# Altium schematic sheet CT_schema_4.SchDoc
size 401 x 230 mm
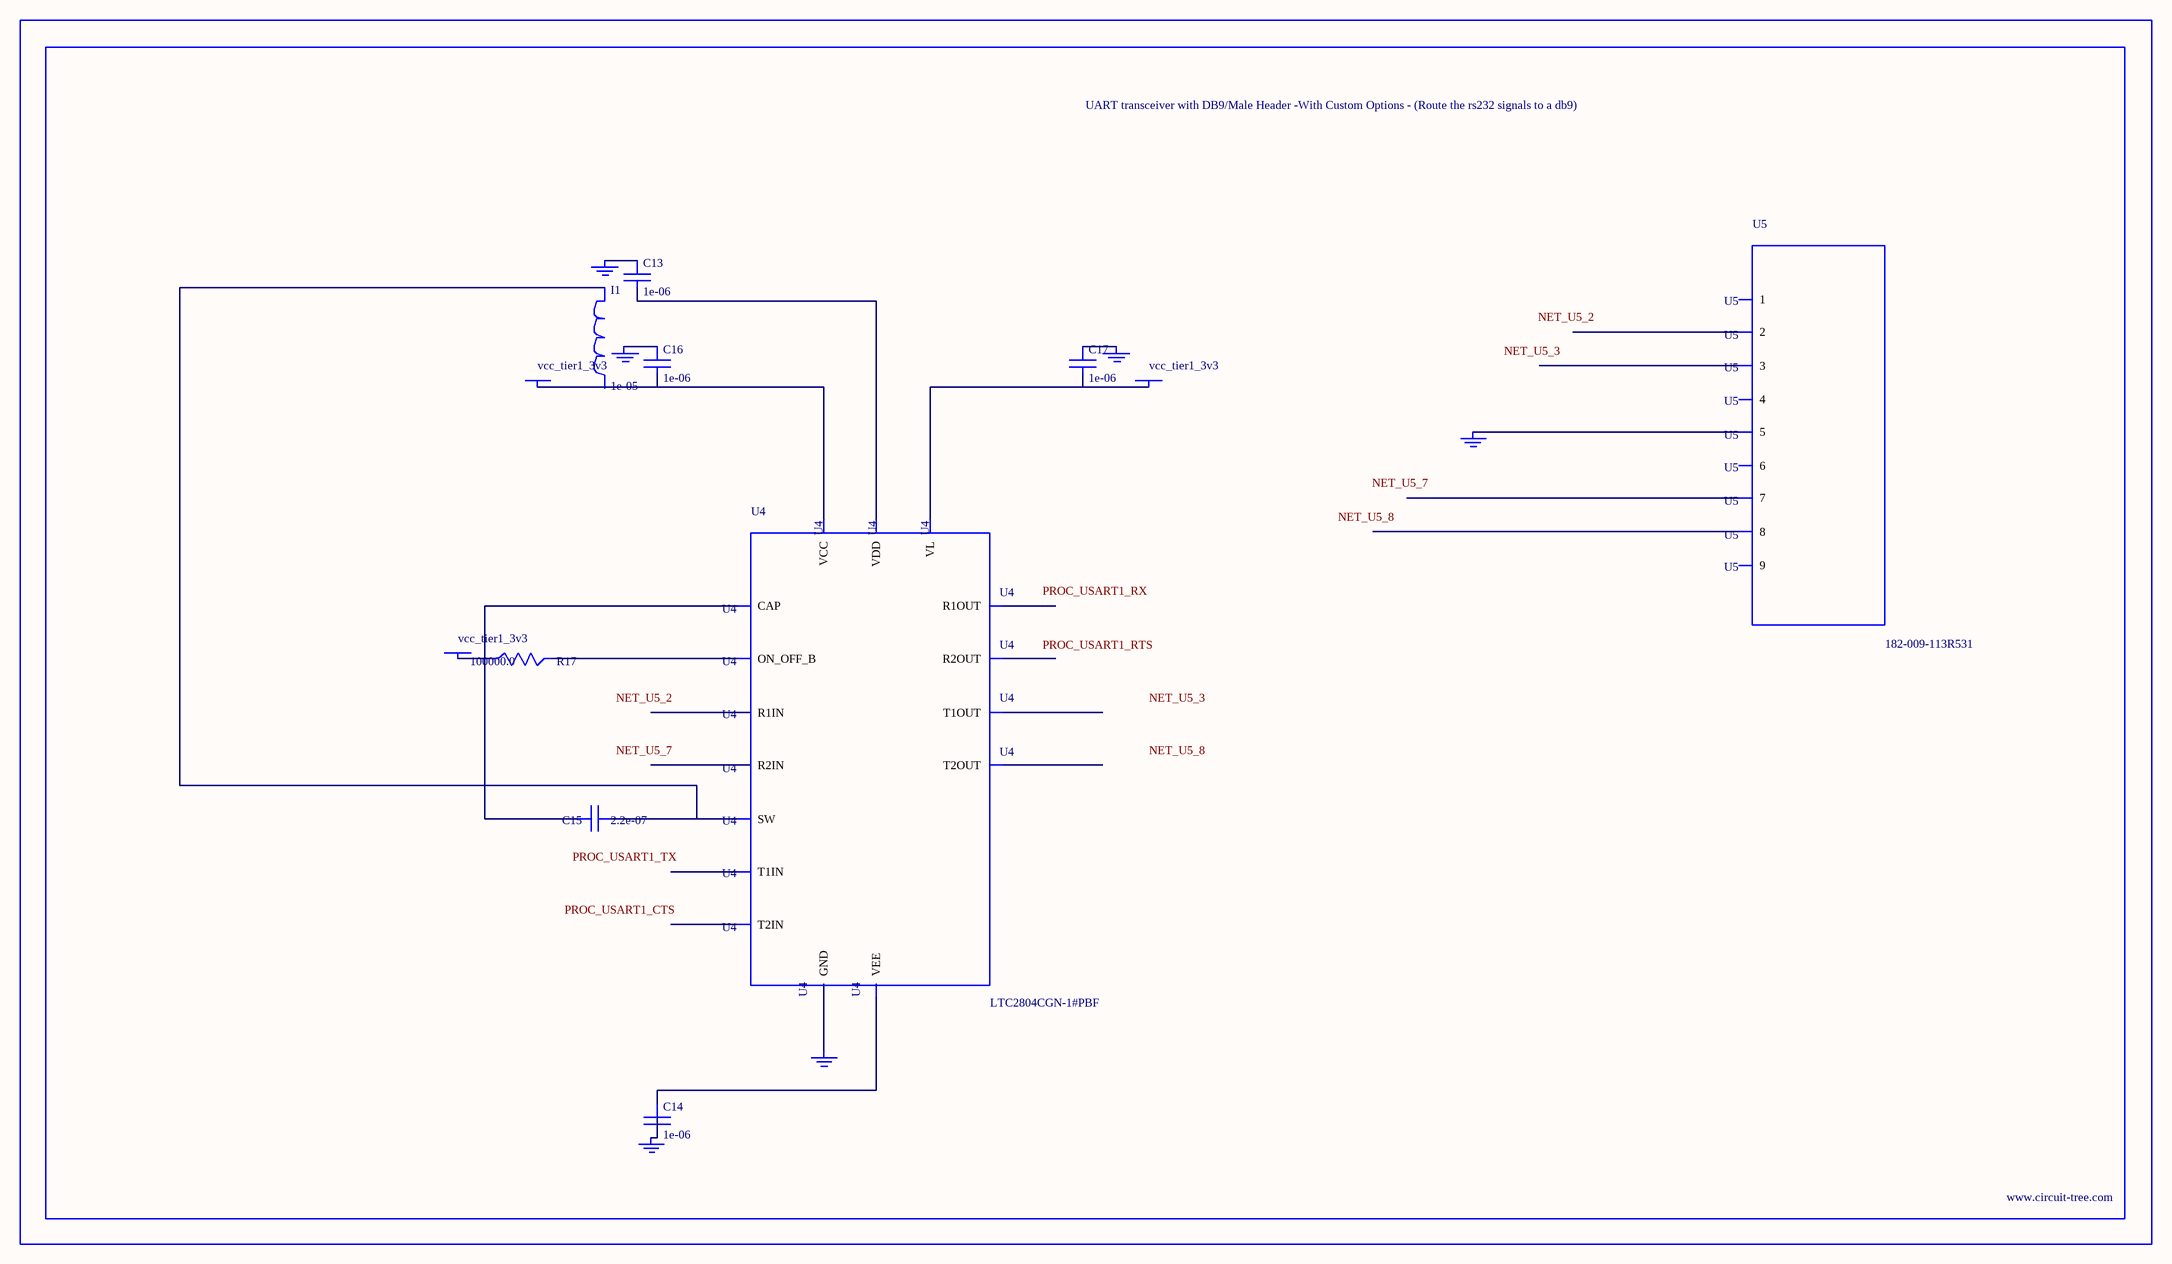
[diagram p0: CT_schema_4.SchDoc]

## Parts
BORDER3  (no value)
C13  1e-06  [C0603]
C14  1e-06  [C0603]
C15  2.2e-07  [C0603]
C16  1e-06  [C0603]
C17  1e-06  [C0603]
GND_INSTANCE_3_0  (no value)
GND_INSTANCE_3_1  (no value)
GND_INSTANCE_3_2  (no value)
GND_INSTANCE_3_3  (no value)
GND_INSTANCE_3_4  (no value)
GND_INSTANCE_3_5  (no value)
I1  1e-05  [L1210]
POWER_INSTANCE_3_0  vcc_tier1_3v3
POWER_INSTANCE_3_1  vcc_tier1_3v3
POWER_INSTANCE_3_2  vcc_tier1_3v3
R17  100000.0  [R0603]
U4  LTC2804CGN-1#PBF  [SSOP-16]
U5  182-009-113R531  [182-009-MALE]

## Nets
NetC13_1: C13.1 GND_INSTANCE_3_1.0(GND)
NetC13_2: C13.2 U4.6(VDD)
NetC14_1: C14.1 U4.9(VEE)
NetC14_2: C14.2 GND_INSTANCE_3_2.0(GND)
NetC15_1: C15.1 I1.1 U4.7(SW)
NetC15_2: C15.2 U4.10(CAP)
NetC16_1: C16.1 GND_INSTANCE_3_0.0(GND)
NetC16_2: C16.2 POWER_INSTANCE_3_0.0(PWR) U4.5(VCC)
NetC17_1: C17.1 GND_INSTANCE_3_3.0(GND)
NetC17_2: C17.2 POWER_INSTANCE_3_2.0(PWR) U4.12(VL)
NetGND_INSTANCE_3_4_0: GND_INSTANCE_3_4.0(GND) U4.8(GND)
NetGND_INSTANCE_3_5_0: GND_INSTANCE_3_5.0(GND) U5.5
NetPOWER_INSTANCE_3_1_0: POWER_INSTANCE_3_1.0(PWR) R17.1
NetR17_2: R17.2 U4.11(ON_OFF_B)

Not connected (* = marked no-connect by the designer): I1 2; U4 1(R1IN) 2(R2IN) 3(T1OUT) 4(T2OUT) 13(T2IN) 14(T1IN) 15(R2OUT) 16(R1OUT); U5 1 2 3 4 6 7 8 9

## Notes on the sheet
- Labels drawn without touching a wire or pin: NET_U5_2, NET_U5_3, NET_U5_7, NET_U5_8, PROC_USART1_CTS, PROC_USART1_RTS, PROC_USART1_RX, PROC_USART1_TX

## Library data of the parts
BORDER3 = BORDER_PAGE3
C13 C14 C16 C17 = C0603C105K3RACTU
C15 = C0603C224K3RAC
GND_INSTANCE_3_0-GND_INSTANCE_3_5 = GND
I1 = CBC3225T100MR
POWER_INSTANCE_3_0-POWER_INSTANCE_3_2 = PWR
R17 = RC0603JR-07100KL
